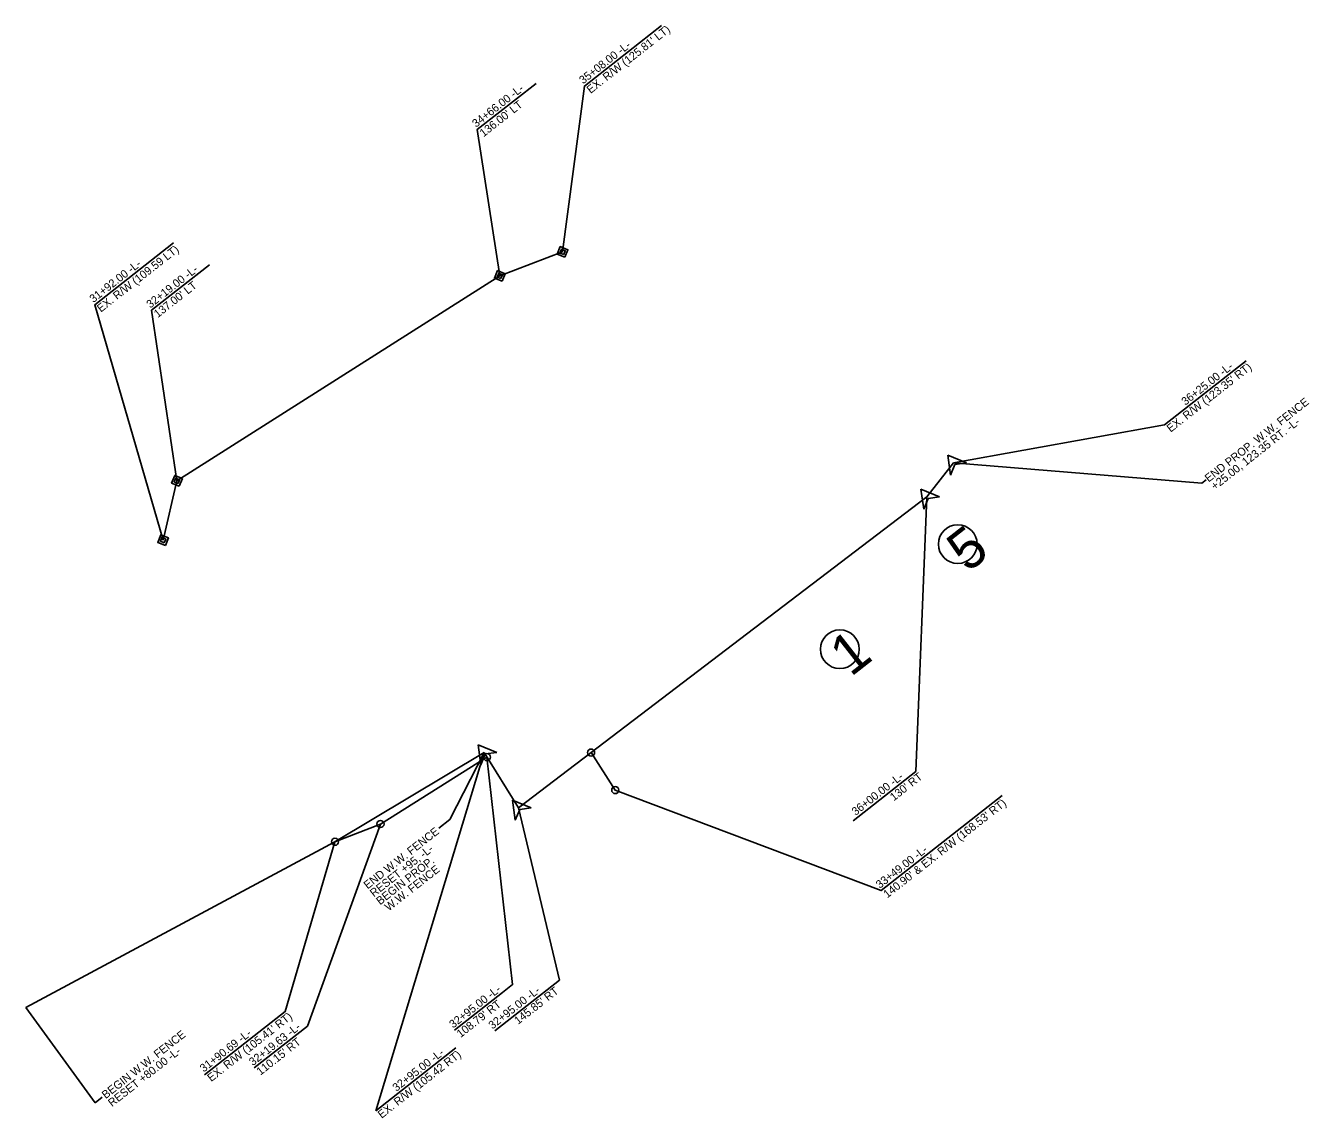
# Model space of a CAD drawing. Extents: x 2175623 to 2194100, y 76458 to 87202.
# Drawn here: x 2175623 to 2176418, y 76458 to 77135 of the extents above; entities that cross this region are included whole.
import ezdxf

# ---------------------------------------------------------------- set-up
doc = ezdxf.new("R2010")
doc.units = 0
for name, color, linetype in [('Exist Plan Preparation Watershed Green', 7, 'Continuous'), ('Exist Plan Preparation Watershed Yellow', 7, 'Continuous'), ('Exist Property Iron Pin CELL', 7, 'Continuous'), ('Prop Drainage Structure Box Number Symbol CELL', 7, 'Continuous'), ('Prop Drainage Structure Pipe RCP 36in Class IV', 7, 'Continuous'), ('Prop Drainage Structure Pipe RCP 42in Class IV', 7, 'Continuous'), ('Prop Drainage Structure Pipe RCP 60in Class IV', 7, 'Continuous'), ('Prop Drainage Structure Pipe Removal Label', 7, 'Continuous'), ('Prop Earthen Structure Base Ditch Special Lateral Detail Label', 7, 'Continuous'), ('Prop Earthen Structure Ditch Flow Line', 7, 'Continuous'), ('Prop Earthen Structure V Ditch Special Lateral Detail Label', 7, 'Continuous'), ('Prop Erosion Rip Rap Pad at Outlet Label', 7, 'Continuous'), ('Prop Plan Preparation Crest Label', 7, 'Continuous'), ('Prop Plan Preparation Sag', 7, 'Continuous'), ('Prop Plan Preparation Sag Label', 7, 'Continuous'), ('Scratch_Level_3', 7, 'Continuous')]:
    doc.layers.add(name, color=color, linetype=linetype)

# ---------------------------------------------------------------- blocks, each defined once
blk = doc.blocks.new('ROW Marker Permanent Easement-E')
at = {"layer": 'Prop Earthen Structure Base Ditch Special Lateral Detail Label'}
for points in [[(0, 0.072), (0.072, 0), (0, -0.072), (-0.072, 0)], [(0, 0.036), (0.036, 0), (0, -0.036), (-0.036, 0)]]:
    blk.add_lwpolyline(points, close=True, dxfattribs=at)
at = {"layer": 'Prop Plan Preparation Crest Label'}
blk.add_line((0, 0), (0, 0), dxfattribs=at)

msp = doc.modelspace()

# ---------------------------------------------------------------- linework, layer by layer
at = {"layer": 'Exist Plan Preparation Watershed Green'}
for p, q in [((2176016.82, 77134.72), (2175969.08, 77097.29)), ((2175939.18, 77098.96), (2175902.78, 77070.43)), ((2175714.64, 77000.12), (2175665.81, 76961.84)), ((2175736.91, 76986.55), (2175701.03, 76958.42))]:
    msp.add_line(p, q, dxfattribs=at)
for points in [[(2176016.82, 77134.72), (2175969.08, 77097.29), (2175955.58, 76994.54)], [(2175939.18, 77098.96), (2175902.78, 77070.43), (2175916.72, 76979.66)], [(2175714.64, 77000.12), (2175665.81, 76961.84), (2175708.16, 76816)], [(2175736.91, 76986.55), (2175701.03, 76958.42), (2175716.79, 76852.78)]]:
    msp.add_lwpolyline(points, dxfattribs=at)
at = {"layer": 'Exist Plan Preparation Watershed Yellow'}
for p, q in [((2176195.83, 76856.25), (2176194.09, 76868.6)), ((2176194.09, 76868.6), (2176205.67, 76863.96)), ((2176198.53, 76862.94), (2176195.83, 76856.25)), ((2176205.67, 76863.96), (2176198.53, 76862.94)), ((2176179.22, 76835.23), (2176177.47, 76847.59)), ((2176177.47, 76847.59), (2176189.05, 76842.94)), ((2176181.91, 76841.92), (2176179.22, 76835.23)), ((2176189.05, 76842.94), (2176181.91, 76841.92)), ((2175905, 76676.87), (2175903.26, 76689.23)), ((2175903.26, 76689.23), (2175914.84, 76684.58)), ((2175914.84, 76684.58), (2175907.7, 76683.56)), ((2175907.7, 76683.56), (2175905, 76676.87)), ((2175926.32, 76642.52), (2175924.58, 76654.87)), ((2175924.58, 76654.87), (2175936.16, 76650.23)), ((2175929.02, 76649.21), (2175926.32, 76642.52)), ((2175936.16, 76650.23), (2175929.02, 76649.21))]:
    msp.add_line(p, q, dxfattribs=at)
at = {"layer": 'Exist Property Iron Pin CELL'}
for centre, radius in [((2175973.26, 76684.43), 2.2), ((2175973.26, 76684.43), 0.0707), ((2175908.74, 76681.64), 2.2), ((2175908.74, 76681.64), 0.0707), ((2175988.21, 76661.19), 2.2), ((2175988.21, 76661.19), 0.0707), ((2175842.82, 76640.18), 2.2), ((2175842.82, 76640.18), 0.0707), ((2175814.63, 76629.21), 2.2), ((2175814.63, 76629.21), 0.0707)]:
    msp.add_circle(centre, radius, dxfattribs=at)
at = {"layer": 'Prop Drainage Structure Box Number Symbol CELL'}
for p, q in [((2176200.35, 76813.56), (2176200.35, 76813.56)), ((2176127.3, 76748.47), (2176127.3, 76748.47))]:
    msp.add_line(p, q, dxfattribs=at)
for centre in [(2176200.35, 76813.56), (2176127.3, 76748.47)]:
    msp.add_circle(centre, 12, dxfattribs=at)
at = {"layer": 'Prop Drainage Structure Pipe RCP 36in Class IV'}
for p, q in [((2175918.42, 76535.87), (2175888.58, 76512.47)), ((2175783.77, 76524), (2175733.89, 76484.9))]:
    msp.add_line(p, q, dxfattribs=at)
for points in [[(2175918.42, 76535.87), (2175924.67, 76540.77), (2175908.74, 76681.64)], [(2175764.58, 76489.16), (2175797.61, 76515.06), (2175842.82, 76640.18)], [(2175733.89, 76484.9), (2175783.77, 76524), (2175814.63, 76629.21)]]:
    msp.add_lwpolyline(points, dxfattribs=at)
at = {"layer": 'Prop Drainage Structure Pipe RCP 42in Class IV'}
msp.add_line((2175988.21, 76661.19), (2175973.26, 76684.43), dxfattribs=at)
at = {"layer": 'Prop Drainage Structure Pipe RCP 60in Class IV'}
msp.add_line((2176227.92, 76657.86), (2176152.8, 76598.97), dxfattribs=at)
msp.add_lwpolyline([(2176227.92, 76657.86), (2176152.8, 76598.97), (2175988.21, 76661.19)], dxfattribs=at)
at = {"layer": 'Prop Drainage Structure Pipe Removal Label'}
for p, q in [((2176197.79, 76863.88), (2176351.52, 76851.26)), ((2176351.52, 76851.26), (2176354.14, 76853.32)), ((2175906.96, 76684.51), (2175885.75, 76642.95)), ((2175879.02, 76637.68), (2175885.75, 76642.95)), ((2175623.08, 76526.53), (2175666.08, 76467.52)), ((2175666.08, 76467.52), (2175670.46, 76470.96))]:
    msp.add_line(p, q, dxfattribs=at)
at = {"layer": 'Prop Earthen Structure Ditch Flow Line'}
for p, q in [((2175916.72, 76979.66), (2175955.58, 76994.54)), ((2175716.79, 76852.78), (2175916.72, 76979.66)), ((2175708.16, 76816), (2175716.79, 76852.78))]:
    msp.add_line(p, q, dxfattribs=at)
at = {"layer": 'Prop Earthen Structure V Ditch Special Lateral Detail Label'}
for p, q in [((2176181.17, 76842.87), (2176197.79, 76863.88)), ((2175928.28, 76650.15), (2176181.17, 76842.87)), ((2175906.96, 76684.51), (2175928.28, 76650.15))]:
    msp.add_line(p, q, dxfattribs=at)
at = {"layer": 'Prop Plan Preparation Sag'}
for p, q in [((2176378.89, 76927.14), (2176328.31, 76887.48)), ((2176197.79, 76863.88), (2176328.31, 76887.48)), ((2176181.17, 76842.87), (2176174.39, 76672.74)), ((2175839.87, 76462.6), (2175906.96, 76684.51)), ((2176174.39, 76672.74), (2176135.47, 76642.23)), ((2175928.28, 76650.15), (2175953.66, 76543.38)), ((2175953.66, 76543.38), (2175913.73, 76512.07)), ((2175839.87, 76462.6), (2175889.49, 76501.5))]:
    msp.add_line(p, q, dxfattribs=at)
at = {"layer": 'Prop Plan Preparation Sag Label'}
for p, q in [((2175842.82, 76640.18), (2175908.74, 76681.64)), ((2175814.63, 76629.21), (2175842.82, 76640.18))]:
    msp.add_line(p, q, dxfattribs=at)
at = {"layer": 'Scratch_Level_3'}
for p, q in [((2176181.17, 76842.87), (2176197.79, 76863.88)), ((2175928.28, 76650.15), (2176181.17, 76842.87)), ((2175814.63, 76629.21), (2175906.96, 76684.51)), ((2175906.96, 76684.51), (2175928.28, 76650.15)), ((2175623.08, 76526.53), (2175814.63, 76629.21))]:
    msp.add_line(p, q, dxfattribs=at)

# ---------------------------------------------------------------- block references
at = {"layer": 'Prop Plan Preparation Sag Label', "xscale": 49.99999999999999, "yscale": 50.00000000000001, "rotation": -156.87942851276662}
for p in [(2175955.58, 76994.54), (2175916.72, 76979.66), (2175716.79, 76852.78), (2175708.16, 76816)]:
    msp.add_blockref('ROW Marker Permanent Easement-E', p, dxfattribs=at)

# ---------------------------------------------------------------- texts
at = {"layer": 'Exist Plan Preparation Watershed Green'}
for s, p in [("EX. R/W (125.81' LT)", (2175972.94, 77092.38)), ('35+08.00 -L-', (2175968.31, 77098.28)), ('34+66.00 -L-', (2175902.01, 77071.41)), ("136.00' LT", (2175906.64, 77065.51)), ('EX. R/W (109.59 LT)', (2175669.67, 76956.92)), ('31+92.00 -L-', (2175665.04, 76962.82)), ('32+19.00 -L-', (2175700.25, 76959.41)), ("137.00' LT", (2175704.88, 76953.5))]:
    msp.add_text(s, height=5, rotation=38.0951, dxfattribs=at).set_placement(p)
at = {"layer": 'Prop Drainage Structure Pipe RCP 36in Class IV'}
for s, p in [('32+95.00 -L-', (2175887.81, 76513.46)), ("108.79' RT", (2175892.43, 76507.56)), ("EX. R/W (105.41' RT)", (2175737.99, 76480.28)), ('31+90.69 -L-', (2175733.36, 76486.19)), ('32+19.63 -L-', (2175763.8, 76490.14)), ("110.15' RT", (2175768.43, 76484.24))]:
    msp.add_text(s, height=5, rotation=38.0951, dxfattribs=at).set_placement(p)
at = {"layer": 'Prop Drainage Structure Pipe RCP 60in Class IV'}
for s, p in [("140.90' & EX. R/W (168.53' RT)", (2176156.66, 76594.05)), ('33+49.00 -L-', (2176152.03, 76599.96))]:
    msp.add_text(s, height=5, rotation=38.0951, dxfattribs=at).set_placement(p)
at = {"layer": 'Prop Drainage Structure Pipe Removal Label'}
for s, p in [('END PROP. W.W. FENCE ', (2176355.73, 76851.68)), ('+25.00, 123.35 RT. -L-', (2176359.58, 76846.76)), ('END W.W. FENCE', (2175834.85, 76599.61)), ('RESET +95, -L-', (2175838.71, 76594.69)), ('BEGIN PROP.', (2175842.57, 76589.77)), (' W.W. FENCE', (2175846.42, 76584.86)), ('BEGIN W.W. FENCE', (2175672.67, 76469.69)), ('RESET +80.00 -L-', (2175676.53, 76464.77))]:
    msp.add_text(s, height=5, rotation=38.0951, dxfattribs=at).set_placement(p)
at = {"layer": 'Prop Erosion Rip Rap Pad at Outlet Label'}
for s, p in [('5', (2176206.47, 76795.55)), ('1', (2176134.05, 76730.95))]:
    msp.add_text(s, height=25, rotation=38.0951, dxfattribs=at).set_placement(p)
at = {"layer": 'Prop Plan Preparation Sag'}
for s, p in [("EX. R/W (123.35' RT)", (2176332.17, 76882.56)), ('36+25.00 -L- ', (2176341.28, 76899.23)), ('36+00.00 -L- ', (2176137.07, 76645.18)), ("130' RT", (2176160.75, 76654.21)), ('32+95.00 -L- ', (2175912.13, 76512.81)), ("145.85' RT", (2175928.03, 76515.74)), ('EX. R/W (105.42 RT)', (2175843.55, 76457.54)), ('32+95.00 -L-', (2175852.66, 76474.21))]:
    msp.add_text(s, height=5, rotation=38.0951, dxfattribs=at).set_placement(p)

doc.saveas('drawing.dxf')
